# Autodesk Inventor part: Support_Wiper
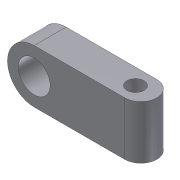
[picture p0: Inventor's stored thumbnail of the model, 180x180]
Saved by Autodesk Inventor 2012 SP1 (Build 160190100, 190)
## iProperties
Created: 2006-03
Part Number: Support_Wiper
Document SubType Name: Modeling
Material: Stainless Steel, 440C
Mass: 138.885 g
Surface Area: 61.269 cm^2
Volume: 17.9206 cm^3
Density: 7.75 g/cm^3
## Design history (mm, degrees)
sketch "Sketch1"
  geometry: L1 (-43.75, 0)-(43.75, 0) reference; L2 (25, 12.5)-(-25, 12.5); L3 (-25, 12.5)-(-25, -12.5); L4 (-25, -12.5)-(25, -12.5); L5 (25, -12.5)-(25, 12.5); L6 (25, 12.5)-(-25, -12.5); A1 r 12.5 centre (25, 0) between (25, -12.5) and (25, 12.5); 1 further point
  constraints: 10 end point, 2 midpoint, 2 parallel, 2 point on circle, 1 centre point, 1 horizontal, 1 perpendicular, 1 point on line
  dimensions: "d11" = 25 distance of L4.end L2.start; "d12" = 50 distance of L2.start L2.end
extrude "Extrusion1" new body sketch "Sketch1" stored distance "d3" = 15; taper "d4" = 0 deg
sketch "Sketch4"
  geometry: C1 r 7.5 at (25, 0); A1 r 12.5 centre (25, 0) between (25, -12.5) and (25, 12.5) reference; 1 further point
  constraints: 1 centre point, 1 coincident
  dimensions: "d13" = 15 diameter of C1
extrude "Extrusion3" cut sketch "Sketch4" stored distance "d14" = 15; taper "d15" = 0 deg
sketch "Sketch3"
  geometry: L1 (-2.5, 0)-(32.5, 0) reference; L2 (25, -7.5)-(25, 7.5) reference; C1 r 4 at (15, 0); 1 further point
  constraints: 1 centre point, 1 midpoint
  dimensions: "d8" = 8 diameter of C1; "d16" = 10 distance from line of L2 C1.centre
extrude "Extrusion2" cut sketch "Sketch3" stored distance "d9" = 15; taper "d10" = 0 deg
fillet "Fillet2"
body "Solid1"
